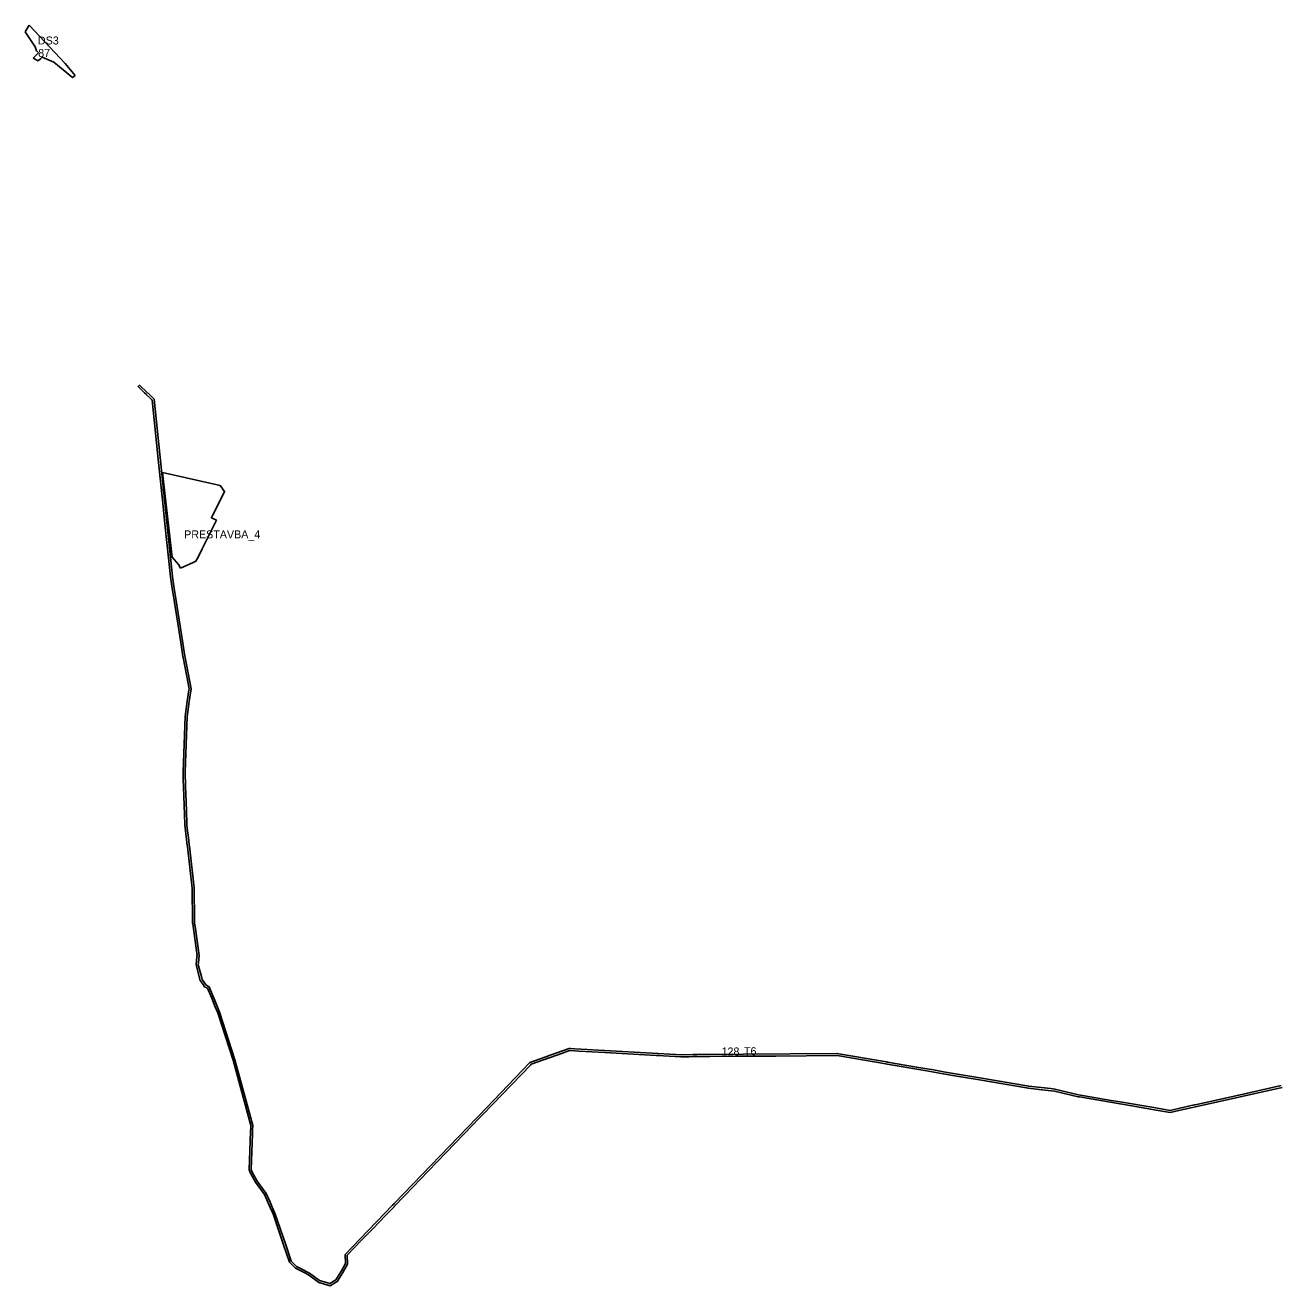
# Model space of a CAD drawing. Extents: x -477001 to -465642, y -1158278 to -1150672.
# Drawn here: x -474281 to -472407, y -1157065 to -1155175 of the extents above; entities that cross this region are included whole.
import ezdxf

# ---------------------------------------------------------------- set-up
doc = ezdxf.new("R2010")
doc.units = 0
for name, color, linetype in [('prestavba_n', 7, 'Continuous'), ('VPS_id', 7, 'Continuous'), ('VPS_n', 7, 'Continuous'), ('vyvlastneni_n', 7, 'Continuous')]:
    doc.layers.add(name, color=color, linetype=linetype)

msp = doc.modelspace()

# ---------------------------------------------------------------- linework, layer by layer
at = {"layer": 'prestavba_n'}
for p, q in [((-474075.4, -1155845.8), (-474071.8, -1155876.6)), ((-474015.7, -1155960.5), (-473994, -1155917.5)), ((-474023.3, -1155975.5), (-474019.8, -1155968.6)), ((-474019.8, -1155968.6), (-474015.7, -1155960.5)), ((-474060.5, -1155972.9), (-474051, -1155983.7)), ((-474051, -1155983.7), (-474048.3, -1155989.4))]:
    msp.add_line(p, q, dxfattribs=at)
for points in [[(-473994, -1155917.5), (-474001.8, -1155913.7), (-473982, -1155874.5), (-473988.5, -1155865.4), (-474075.4, -1155845.8)], [(-474071.8, -1155876.6), (-474062.1, -1155959.9), (-474060.5, -1155972.9)], [(-474048.3, -1155989.4), (-474029.2, -1155980.7), (-474025, -1155978.8), (-474023.3, -1155975.5)]]:
    msp.add_lwpolyline(points, dxfattribs=at)
at = {"layer": 'VPS_n'}
for p, q in [((-474275, -1155175.1), (-474281.1, -1155184.9)), ((-474259.9, -1155191.7), (-474275, -1155175.1)), ((-474221.4, -1155232.3), (-474259.9, -1155191.7)), ((-474263.8, -1155219.1), (-474269.4, -1155224.4)), ((-474269.4, -1155224.4), (-474261.5, -1155228.7)), ((-474264.2, -1155213.6), (-474261.4, -1155216.7)), ((-474261.4, -1155216.7), (-474263.8, -1155219.1)), ((-474261.5, -1155228.7), (-474258.3, -1155225.4)), ((-474258.3, -1155225.4), (-474255.9, -1155222.9)), ((-474255.9, -1155222.9), (-474238.1, -1155230.3)), ((-474206.2, -1155250.3), (-474221.4, -1155232.3))]:
    msp.add_line(p, q, dxfattribs=at)
for points in [[(-474281.1, -1155184.9), (-474266.3, -1155207.3), (-474264.2, -1155213.6)], [(-474238.1, -1155230.3), (-474210.1, -1155253.7), (-474206.2, -1155250.3)], [(-472397.4, -1156765.2), (-472460.9, -1156779.4), (-472526.5, -1156794.1), (-472527.6, -1156794.3), (-472544.8, -1156798.2), (-472547.5, -1156798.8), (-472563.9, -1156802.5), (-472588.1, -1156798.3), (-472638.8, -1156789.7), (-472652.3, -1156787.4), (-472695.3, -1156780), (-472701.2, -1156779), (-472736.6, -1156770.4), (-472743, -1156769.7), (-472757.3, -1156768.2), (-472775.9, -1156766.3), (-472852.3, -1156753.2), (-472886, -1156747.5), (-472903.9, -1156744.4), (-472919, -1156741.8), (-472944.1, -1156737.5), (-472987.6, -1156730.1), (-472989.5, -1156729.8), (-473063.6, -1156717.1), (-473273.7, -1156718.8), (-473279.9, -1156718.8), (-473296.3, -1156719), (-473456.6, -1156710.2), (-473463.2, -1156709.8), (-473465.3, -1156709.7), (-473493.6, -1156719.8), (-473500.2, -1156722.2), (-473524.1, -1156730.8), (-473600.4, -1156810.1), (-473603.6, -1156813.4), (-473727.1, -1156941.6), (-473728.3, -1156942.9), (-473730, -1156944.6), (-473778.6, -1156995.1), (-473801.2, -1157018.6), (-473800.5, -1157032.2), (-473806.8, -1157042.8), (-473815, -1157056.7), (-473824.1, -1157062.2), (-473839.6, -1157057.7), (-473854.5, -1157046.3), (-473869.3, -1157038.9), (-473872.3, -1157037.4), (-473874, -1157036.5), (-473882, -1157028.4), (-473882, -1157028.3), (-473890.3, -1157004.1), (-473906.1, -1156957.8), (-473910.7, -1156947.3), (-473913.9, -1156940.2), (-473919.8, -1156926.8), (-473933, -1156908.6), (-473940.7, -1156895.2), (-473942.1, -1156891), (-473940.3, -1156837.6), (-473940.1, -1156831.8), (-473939.8, -1156825), (-473966.5, -1156726.5), (-473989.5, -1156655.1), (-473997.9, -1156635), (-474003.3, -1156621.9), (-474005.3, -1156617.2), (-474009.9, -1156614.6), (-474015.7, -1156606.3), (-474016.9, -1156601.8), (-474021.6, -1156583.9), (-474021.4, -1156581.3), (-474020.4, -1156570.2), (-474026.4, -1156526.1), (-474026.6, -1156525.1), (-474027.2, -1156520.2), (-474027.4, -1156519.1), (-474027.4, -1156517.6), (-474027.8, -1156468.8), (-474034.4, -1156410.6), (-474034.9, -1156406.2), (-474035, -1156405.3), (-474035.8, -1156397.9), (-474038, -1156379.2), (-474038.5, -1156374.8), (-474038.7, -1156372.4), (-474039.4, -1156353), (-474040.2, -1156327.9), (-474040.6, -1156317.2), (-474041.4, -1156294.8), (-474038.1, -1156212.2), (-474035, -1156189.3), (-474034.1, -1156182.8), (-474032.3, -1156170.5), (-474041.2, -1156123.4), (-474041.6, -1156121.3), (-474043.1, -1156112), (-474045.2, -1156098.3), (-474051.7, -1156057.5), (-474055.7, -1156031.7), (-474057.6, -1156019.7), (-474059.8, -1156006), (-474060.4, -1156001.9), (-474063.4, -1155973.3), (-474073.3, -1155876.8), (-474074, -1155869.9), (-474074.3, -1155866.6), (-474087.7, -1155735.8), (-474089.6, -1155734), (-474094.8, -1155729.1), (-474099.7, -1155724.5), (-474108.1, -1155716.5), (-474109.8, -1155714.9), (-474111.8, -1155717.1), (-474109.4, -1155719.4), (-474102.1, -1155726.3), (-474099.1, -1155729.1), (-474099, -1155729.3), (-474094.1, -1155733.9), (-474090.6, -1155737.2), (-474081, -1155830.7), (-474074.8, -1155891.7), (-474073.7, -1155902.2), (-474071.1, -1155927.6), (-474066.4, -1155973.6), (-474063.4, -1156002.3), (-474062.9, -1156005.7), (-474060.6, -1156019.9), (-474058.8, -1156031.5), (-474047.9, -1156101), (-474044.6, -1156121.8), (-474044.3, -1156123.5), (-474038.9, -1156151.6), (-474035.3, -1156170.5), (-474035.6, -1156172.4), (-474038, -1156188.9), (-474041.1, -1156211.9), (-474044.4, -1156294.7), (-474044, -1156306), (-474043.6, -1156317.1), (-474041.7, -1156372.6), (-474041.5, -1156374.4), (-474041, -1156378.9), (-474038.1, -1156405), (-474037.8, -1156407.1), (-474030.8, -1156469), (-474030.4, -1156519.3), (-474030.1, -1156521.2), (-474029.9, -1156522.8), (-474023.4, -1156570.3), (-474023.5, -1156571.4), (-474024.6, -1156584.2), (-474018.5, -1156607.5), (-474014.3, -1156613.5), (-474012, -1156616.9), (-474007.6, -1156619.3), (-474001.4, -1156634.3), (-473996.1, -1156647), (-473992.3, -1156656.2), (-473969.3, -1156727.3), (-473942.8, -1156825.3), (-473942.9, -1156828.4), (-473943.1, -1156834.3), (-473945.1, -1156891.4), (-473943.4, -1156896.5), (-473935.5, -1156910.2), (-473922.4, -1156928.3), (-473913.6, -1156948.2), (-473910.3, -1156955.7), (-473908.9, -1156958.9), (-473893.5, -1157004.1), (-473884.6, -1157030), (-473882.6, -1157032), (-473875.8, -1157038.9), (-473874.8, -1157039.5), (-473862.8, -1157045.5), (-473856.1, -1157048.9), (-473840.9, -1157060.4), (-473823.6, -1157065.4), (-473814, -1157059.6), (-473812.8, -1157058.9), (-473812, -1157057.5), (-473804.9, -1157045.5), (-473797.5, -1157032.9), (-473798.1, -1157019.7), (-473776.5, -1156997.2), (-473759.2, -1156979.3), (-473741, -1156960.4), (-473736.9, -1156956.2), (-473727.9, -1156946.8), (-473727.8, -1156946.7), (-473726.1, -1156944.9), (-473714.1, -1156932.4), (-473711.4, -1156929.7), (-473676.5, -1156893.4), (-473649.6, -1156865.5), (-473610.4, -1156824.7), (-473600.7, -1156814.7), (-473594.4, -1156808.2), (-473523.4, -1156734.4), (-473522.4, -1156733.3), (-473475.2, -1156716.4), (-473464.9, -1156712.7), (-473457.3, -1156713.2), (-473450.9, -1156713.5), (-473411.6, -1156715.7), (-473334.8, -1156719.9), (-473330.5, -1156720.1), (-473323.8, -1156720.5), (-473315.3, -1156720.9), (-473306.4, -1156721.4), (-473305.6, -1156721.5), (-473297.9, -1156721.9), (-473296.4, -1156722), (-473285.5, -1156721.9), (-473279.3, -1156721.8), (-473254.2, -1156721.6), (-473214.7, -1156721.3), (-473209.8, -1156721.3), (-473168.8, -1156721), (-473155.5, -1156720.9), (-473063.8, -1156720.1), (-473060.1, -1156720.8), (-472990.4, -1156732.7), (-472988.3, -1156733), (-472931.6, -1156742.7), (-472904.4, -1156747.4), (-472880.6, -1156751.4), (-472852.9, -1156756.1), (-472776.4, -1156769.2), (-472756.1, -1156771.4), (-472742, -1156772.9), (-472737.1, -1156773.4), (-472701.8, -1156782), (-472699.7, -1156782.3), (-472638.9, -1156792.7), (-472621.3, -1156795.7), (-472585, -1156801.9), (-472563.9, -1156805.5), (-472544.3, -1156801.1), (-472541.6, -1156800.5), (-472530.3, -1156798), (-472516.7, -1156795), (-472460.9, -1156782.5), (-472395.9, -1156767.9)]]:
    msp.add_lwpolyline(points, dxfattribs=at)
at = {"layer": 'vyvlastneni_n'}
for p, q in [((-474275, -1155175.1), (-474281.1, -1155184.9)), ((-474259.9, -1155191.7), (-474275, -1155175.1)), ((-474221.4, -1155232.3), (-474259.9, -1155191.7)), ((-474263.8, -1155219.1), (-474269.4, -1155224.4)), ((-474269.4, -1155224.4), (-474261.5, -1155228.7)), ((-474264.2, -1155213.6), (-474261.4, -1155216.7)), ((-474261.4, -1155216.7), (-474263.8, -1155219.1)), ((-474261.5, -1155228.7), (-474258.3, -1155225.4)), ((-474258.3, -1155225.4), (-474255.9, -1155222.9)), ((-474255.9, -1155222.9), (-474238.1, -1155230.3)), ((-474206.2, -1155250.3), (-474221.4, -1155232.3))]:
    msp.add_line(p, q, dxfattribs=at)
for points in [[(-474281.1, -1155184.9), (-474266.3, -1155207.3), (-474264.2, -1155213.6)], [(-474238.1, -1155230.3), (-474210.1, -1155253.7), (-474206.2, -1155250.3)], [(-472397.4, -1156765.2), (-472460.9, -1156779.4), (-472526.5, -1156794.1), (-472527.6, -1156794.3), (-472544.8, -1156798.2), (-472547.5, -1156798.8), (-472563.9, -1156802.5), (-472588.1, -1156798.3), (-472638.8, -1156789.7), (-472652.3, -1156787.4), (-472695.3, -1156780), (-472701.2, -1156779), (-472736.6, -1156770.4), (-472743, -1156769.7), (-472757.3, -1156768.2), (-472775.9, -1156766.3), (-472852.3, -1156753.2), (-472886, -1156747.5), (-472903.9, -1156744.4), (-472919, -1156741.8), (-472944.1, -1156737.5), (-472987.6, -1156730.1), (-472989.5, -1156729.8), (-473063.6, -1156717.1), (-473273.7, -1156718.8), (-473279.9, -1156718.8), (-473296.3, -1156719), (-473456.6, -1156710.2), (-473463.2, -1156709.8), (-473465.3, -1156709.7), (-473493.6, -1156719.8), (-473500.2, -1156722.2), (-473524.1, -1156730.8), (-473600.4, -1156810.1), (-473603.6, -1156813.4), (-473727.1, -1156941.6), (-473728.3, -1156942.9), (-473730, -1156944.6), (-473778.6, -1156995.1), (-473801.2, -1157018.6), (-473800.5, -1157032.2), (-473806.8, -1157042.8), (-473815, -1157056.7), (-473824.1, -1157062.2), (-473839.6, -1157057.7), (-473854.5, -1157046.3), (-473869.3, -1157038.9), (-473872.3, -1157037.4), (-473874, -1157036.5), (-473882, -1157028.4), (-473882, -1157028.3), (-473890.3, -1157004.1), (-473906.1, -1156957.8), (-473910.7, -1156947.3), (-473913.9, -1156940.2), (-473919.8, -1156926.8), (-473933, -1156908.6), (-473940.7, -1156895.2), (-473942.1, -1156891), (-473940.3, -1156837.6), (-473940.1, -1156831.8), (-473939.8, -1156825), (-473966.5, -1156726.5), (-473989.5, -1156655.1), (-473997.9, -1156635), (-474003.3, -1156621.9), (-474005.3, -1156617.2), (-474009.9, -1156614.6), (-474015.7, -1156606.3), (-474016.9, -1156601.8), (-474021.6, -1156583.9), (-474021.4, -1156581.3), (-474020.4, -1156570.2), (-474026.4, -1156526.1), (-474026.6, -1156525.1), (-474027.2, -1156520.2), (-474027.4, -1156519.1), (-474027.4, -1156517.6), (-474027.8, -1156468.8), (-474034.4, -1156410.6), (-474034.9, -1156406.2), (-474035, -1156405.3), (-474035.8, -1156397.9), (-474038, -1156379.2), (-474038.5, -1156374.8), (-474038.7, -1156372.4), (-474039.4, -1156353), (-474040.2, -1156327.9), (-474040.6, -1156317.2), (-474041.4, -1156294.8), (-474038.1, -1156212.2), (-474035, -1156189.3), (-474034.1, -1156182.8), (-474032.3, -1156170.5), (-474041.2, -1156123.4), (-474041.6, -1156121.3), (-474043.1, -1156112), (-474045.2, -1156098.3), (-474051.7, -1156057.5), (-474055.7, -1156031.7), (-474057.6, -1156019.7), (-474059.8, -1156006), (-474060.4, -1156001.9), (-474063.4, -1155973.3), (-474073.3, -1155876.8), (-474074, -1155869.9), (-474074.3, -1155866.6), (-474087.7, -1155735.8), (-474089.6, -1155734), (-474094.8, -1155729.1), (-474099.7, -1155724.5), (-474108.1, -1155716.5), (-474109.8, -1155714.9), (-474111.8, -1155717.1), (-474109.4, -1155719.4), (-474102.1, -1155726.3), (-474099.1, -1155729.1), (-474099, -1155729.3), (-474094.1, -1155733.9), (-474090.6, -1155737.2), (-474081, -1155830.7), (-474074.8, -1155891.7), (-474073.7, -1155902.2), (-474071.1, -1155927.6), (-474066.4, -1155973.6), (-474063.4, -1156002.3), (-474062.9, -1156005.7), (-474060.6, -1156019.9), (-474058.8, -1156031.5), (-474047.9, -1156101), (-474044.6, -1156121.8), (-474044.3, -1156123.5), (-474038.9, -1156151.6), (-474035.3, -1156170.5), (-474035.6, -1156172.4), (-474038, -1156188.9), (-474041.1, -1156211.9), (-474044.4, -1156294.7), (-474044, -1156306), (-474043.6, -1156317.1), (-474041.7, -1156372.6), (-474041.5, -1156374.4), (-474041, -1156378.9), (-474038.1, -1156405), (-474037.8, -1156407.1), (-474030.8, -1156469), (-474030.4, -1156519.3), (-474030.1, -1156521.2), (-474029.9, -1156522.8), (-474023.4, -1156570.3), (-474023.5, -1156571.4), (-474024.6, -1156584.2), (-474018.5, -1156607.5), (-474014.3, -1156613.5), (-474012, -1156616.9), (-474007.6, -1156619.3), (-474001.4, -1156634.3), (-473996.1, -1156647), (-473992.3, -1156656.2), (-473969.3, -1156727.3), (-473942.8, -1156825.3), (-473942.9, -1156828.4), (-473943.1, -1156834.3), (-473945.1, -1156891.4), (-473943.4, -1156896.5), (-473935.5, -1156910.2), (-473922.4, -1156928.3), (-473913.6, -1156948.2), (-473910.3, -1156955.7), (-473908.9, -1156958.9), (-473893.5, -1157004.1), (-473884.6, -1157030), (-473882.6, -1157032), (-473875.8, -1157038.9), (-473874.8, -1157039.5), (-473862.8, -1157045.5), (-473856.1, -1157048.9), (-473840.9, -1157060.4), (-473823.6, -1157065.4), (-473814, -1157059.6), (-473812.8, -1157058.9), (-473812, -1157057.5), (-473804.9, -1157045.5), (-473797.5, -1157032.9), (-473798.1, -1157019.7), (-473776.5, -1156997.2), (-473759.2, -1156979.3), (-473741, -1156960.4), (-473736.9, -1156956.2), (-473727.9, -1156946.8), (-473727.8, -1156946.7), (-473726.1, -1156944.9), (-473714.1, -1156932.4), (-473711.4, -1156929.7), (-473676.5, -1156893.4), (-473649.6, -1156865.5), (-473610.4, -1156824.7), (-473600.7, -1156814.7), (-473594.4, -1156808.2), (-473523.4, -1156734.4), (-473522.4, -1156733.3), (-473475.2, -1156716.4), (-473464.9, -1156712.7), (-473457.3, -1156713.2), (-473450.9, -1156713.5), (-473411.6, -1156715.7), (-473334.8, -1156719.9), (-473330.5, -1156720.1), (-473323.8, -1156720.5), (-473315.3, -1156720.9), (-473306.4, -1156721.4), (-473305.6, -1156721.5), (-473297.9, -1156721.9), (-473296.4, -1156722), (-473285.5, -1156721.9), (-473279.3, -1156721.8), (-473254.2, -1156721.6), (-473214.7, -1156721.3), (-473209.8, -1156721.3), (-473168.8, -1156721), (-473155.5, -1156720.9), (-473063.8, -1156720.1), (-473060.1, -1156720.8), (-472990.4, -1156732.7), (-472988.3, -1156733), (-472931.6, -1156742.7), (-472904.4, -1156747.4), (-472880.6, -1156751.4), (-472852.9, -1156756.1), (-472776.4, -1156769.2), (-472756.1, -1156771.4), (-472742, -1156772.9), (-472737.1, -1156773.4), (-472701.8, -1156782), (-472699.7, -1156782.3), (-472638.9, -1156792.7), (-472621.3, -1156795.7), (-472585, -1156801.9), (-472563.9, -1156805.5), (-472544.3, -1156801.1), (-472541.6, -1156800.5), (-472530.3, -1156798), (-472516.7, -1156795), (-472460.9, -1156782.5), (-472395.9, -1156767.9)]]:
    msp.add_lwpolyline(points, dxfattribs=at)

# ---------------------------------------------------------------- texts
at = {"layer": 'prestavba_n'}
msp.add_text('PRESTAVBA_4', height=12, dxfattribs=at).set_placement((-474042.7, -1155944.6))
at = {"layer": 'VPS_id'}
for s, p in [('87', (-474261.6, -1155222.7)), ('128', (-473236.7, -1156720.1))]:
    msp.add_text(s, height=12, dxfattribs=at).set_placement(p)
at = {"layer": 'VPS_n'}
for s, p in [('DS3', (-474262, -1155204)), ('T6', (-473203, -1156719.7))]:
    msp.add_text(s, height=12, dxfattribs=at).set_placement(p)

doc.saveas('drawing.dxf')
